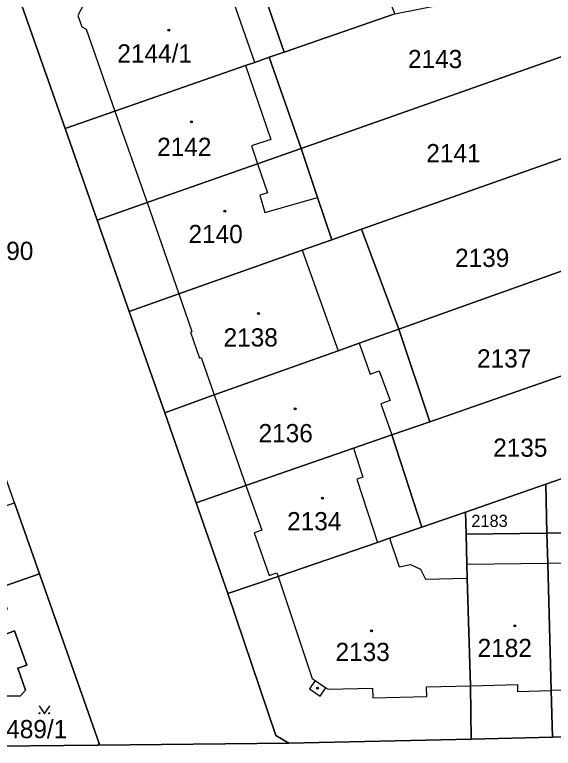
# Model space of a CAD drawing. Extents: x -596233 to -595156, y -1161235 to -1159375.
# Drawn here: x -595851.8 to -595801.6, y -1160886.7 to -1160818.3 of the extents above; entities that cross this region are included whole.
import ezdxf

# ---------------------------------------------------------------- set-up
doc = ezdxf.new("R2010")
doc.units = 0
for name, color, linetype in [('KN_CAR_KR', 7, 'Continuous'), ('KN_KULTURY', 7, 'Continuous'), ('KN_PARC_CIS_POZ', 7, 'Continuous'), ('KN_PARC_CIS_STAV', 7, 'Continuous'), ('KN_PARC_PLOCHA', 7, 'Continuous'), ('parcely_l', 7, 'Continuous')]:
    doc.layers.add(name, color=color, linetype=linetype)

msp = doc.modelspace()

# ---------------------------------------------------------------- linework, layer by layer
at = {"layer": 'KN_CAR_KR'}
for points in [[(-595829.44, -1160822.7), (-595832.08, -1160815.13)], [(-595845.38, -1160817.27), (-595845.92, -1160818.32)], [(-595845.92, -1160818.32), (-595845.55, -1160819.38)], [(-595845.55, -1160819.38), (-595845.14, -1160819.61)], [(-595845.14, -1160819.61), (-595842.47, -1160827.25)], [(-595830.29, -1160823), (-595827.95, -1160829.88)], [(-595842.47, -1160827.25), (-595839.48, -1160835.77)], [(-595827.95, -1160829.88), (-595829.75, -1160830.49)], [(-595829.75, -1160830.49), (-595829.19, -1160832.15)], [(-595829.19, -1160832.15), (-595828.24, -1160834.87)], [(-595828.24, -1160834.87), (-595828.96, -1160835.08)], [(-595828.96, -1160835.08), (-595828.49, -1160836.71)], [(-595828.49, -1160836.71), (-595823.58, -1160835.31)], [(-595839.48, -1160835.77), (-595836.53, -1160844.3)], [(-595825.01, -1160840.22), (-595821.68, -1160849.61)], [(-595836.53, -1160844.3), (-595835.3, -1160847.8)], [(-595835.3, -1160847.8), (-595835.44, -1160847.85)], [(-595835.44, -1160847.85), (-595834.58, -1160850.28)], [(-595819.7, -1160848.9), (-595818.68, -1160851.77)], [(-595834.58, -1160850.28), (-595834.44, -1160850.23)], [(-595834.44, -1160850.23), (-595833.21, -1160853.72)], [(-595818.68, -1160851.77), (-595817.84, -1160851.47)], [(-595817.84, -1160851.47), (-595816.83, -1160854.24)], [(-595833.21, -1160853.72), (-595830.27, -1160862.17)], [(-595816.83, -1160854.24), (-595817.69, -1160854.55)], [(-595817.69, -1160854.55), (-595816.66, -1160857.44)], [(-595820.25, -1160858.69), (-595819.36, -1160861.39)], [(-595819.36, -1160861.39), (-595819.94, -1160861.58)], [(-595819.94, -1160861.58), (-595818.01, -1160867.47)], [(-595830.27, -1160862.17), (-595828.79, -1160866.33)], [(-595828.79, -1160866.33), (-595829.51, -1160866.59)], [(-595829.51, -1160866.59), (-595828.1, -1160870.56)], [(-595816.88, -1160867.08), (-595815.97, -1160869.75)], [(-595815.97, -1160869.75), (-595814.93, -1160869.52)], [(-595814.93, -1160869.52), (-595814.01, -1160869.95)], [(-595809.68, -1160869.5), (-595802.13, -1160869.4)], [(-595802.13, -1160869.4), (-595794.67, -1160869.27)], [(-595828.1, -1160870.56), (-595827.39, -1160870.31)], [(-595827.39, -1160870.31), (-595827.27, -1160870.64)], [(-595814.01, -1160869.95), (-595813.52, -1160870.89)], [(-595827.27, -1160870.64), (-595824.08, -1160880.16)], [(-595813.52, -1160870.89), (-595809.65, -1160870.8)], [(-595823.82, -1160880.34), (-595824.35, -1160881.12)], [(-595824.08, -1160880.16), (-595823.82, -1160880.34)], [(-595823.82, -1160880.34), (-595822.82, -1160881.02)], [(-595809.34, -1160880.83), (-595804.96, -1160880.72)], [(-595804.96, -1160880.72), (-595804.95, -1160881.36)], [(-595824.35, -1160881.12), (-595823.36, -1160881.8)], [(-595823.36, -1160881.8), (-595822.82, -1160881.02)], [(-595822.82, -1160881.02), (-595822.61, -1160881.16)], [(-595822.61, -1160881.16), (-595818.47, -1160881.06)], [(-595818.47, -1160881.06), (-595818.45, -1160881.96)], [(-595813.43, -1160880.93), (-595809.34, -1160880.83)], [(-595813.41, -1160881.83), (-595813.43, -1160880.93)], [(-595804.95, -1160881.36), (-595801.81, -1160881.28)], [(-595798.66, -1160881.2), (-595801.81, -1160881.28)], [(-595818.45, -1160881.96), (-595813.41, -1160881.83)]]:
    msp.add_lwpolyline(points, dxfattribs=at)
at = {"layer": 'KN_KULTURY'}
msp.add_lwpolyline([(-595849.5418, -1160882.7016), (-595849.0418, -1160883.4516), (-595848.5418, -1160882.7016)], dxfattribs=at)
for centre, radius in [((-595837.45, -1160819.71), 0.09), ((-595837.45, -1160819.71), 0.0398), ((-595835.34, -1160828.24), 0.09), ((-595835.34, -1160828.24), 0.0398), ((-595832.24, -1160836.57), 0.09), ((-595832.24, -1160836.57), 0.0398), ((-595829.08, -1160846.12), 0.09), ((-595829.08, -1160846.12), 0.0398), ((-595825.67, -1160855), 0.09), ((-595825.67, -1160855), 0.0398), ((-595823.12, -1160863.34), 0.09), ((-595823.12, -1160863.34), 0.0398), ((-595805.2, -1160875.24), 0.09), ((-595805.2, -1160875.24), 0.0398), ((-595818.57, -1160875.72), 0.09), ((-595818.57, -1160875.72), 0.0398), ((-595823.59, -1160881.06), 0.09), ((-595823.59, -1160881.06), 0.0398), ((-595849.492, -1160883.4014), 0.05), ((-595848.5926, -1160883.4014), 0.05)]:
    msp.add_circle(centre, radius, dxfattribs=at)
at = {"layer": 'KN_PARC_PLOCHA'}
for points in [[(-595851.73, -1160815.7), (-595847.12, -1160828.88), (-595844.13, -1160837.41), (-595841.13, -1160845.93), (-595837.83, -1160855.37), (-595834.9, -1160863.78), (-595831.94, -1160872.24), (-595827.47, -1160885.46), (-595826.28, -1160886.2), (-595844.05, -1160886.38), (-595843.93, -1160886.23), (-595849.5, -1160870.41), (-595851.84, -1160863.77), (-595855.8, -1160852.49), (-595860.43, -1160839.35), (-595862.4, -1160833.66), (-595865.03, -1160826.08), (-595869.66, -1160812.72), (-595870.98, -1160808.89), (-595871.45, -1160807.54), (-595874.31, -1160799.57), (-595859.99, -1160792.1), (-595853.57, -1160810.43)], [(-595820.27, -1160808.95), (-595820.75, -1160809.15), (-595821.96, -1160806.33), (-595826.41, -1160808.2), (-595825.21, -1160811.03), (-595829.99, -1160812.21), (-595826.71, -1160821.75), (-595828.11, -1160822.23), (-595829.44, -1160822.7), (-595830.29, -1160823), (-595842.47, -1160827.25), (-595847.12, -1160828.88), (-595851.73, -1160815.7), (-595833.16, -1160809.18), (-595821.84, -1160805.2)], [(-595816.38, -1160818.19), (-595826.71, -1160821.75), (-595829.99, -1160812.21), (-595825.21, -1160811.03), (-595820.75, -1160809.15), (-595820.27, -1160808.95)], [(-595797.83, -1160821.11), (-595825.12, -1160830.72), (-595828.11, -1160822.23), (-595826.71, -1160821.75), (-595816.38, -1160818.19), (-595807.41, -1160816.36), (-595798.34, -1160814.51)], [(-595797.78, -1160821.87), (-595797.18, -1160829.72), (-595797.13, -1160830.35), (-595819.48, -1160838.26), (-595822.26, -1160839.24), (-595823.58, -1160835.31), (-595825.12, -1160830.72), (-595797.83, -1160821.11)], [(-595825.12, -1160830.72), (-595829.19, -1160832.15), (-595839.48, -1160835.77), (-595844.13, -1160837.41), (-595847.12, -1160828.88), (-595842.47, -1160827.25), (-595830.29, -1160823), (-595829.44, -1160822.7), (-595828.11, -1160822.23)], [(-595822.26, -1160839.24), (-595825.01, -1160840.22), (-595836.53, -1160844.3), (-595841.13, -1160845.93), (-595844.13, -1160837.41), (-595839.48, -1160835.77), (-595829.19, -1160832.15), (-595825.12, -1160830.72), (-595823.58, -1160835.31)], [(-595796.54, -1160838.04), (-595796.35, -1160840.57), (-595816.03, -1160847.59), (-595819.48, -1160838.26), (-595797.13, -1160830.35)], [(-595816.03, -1160847.59), (-595819.7, -1160848.9), (-595821.68, -1160849.61), (-595833.21, -1160853.72), (-595837.83, -1160855.37), (-595841.13, -1160845.93), (-595836.53, -1160844.3), (-595825.01, -1160840.22), (-595822.26, -1160839.24), (-595819.48, -1160838.26)], [(-595795.91, -1160846.33), (-595795.5, -1160850.08), (-595813.12, -1160856.21), (-595816.03, -1160847.59), (-595796.35, -1160840.57)], [(-595813.12, -1160856.21), (-595816.66, -1160857.44), (-595820.25, -1160858.69), (-595830.27, -1160862.17), (-595834.9, -1160863.78), (-595837.83, -1160855.37), (-595833.21, -1160853.72), (-595821.68, -1160849.61), (-595819.7, -1160848.9), (-595816.03, -1160847.59)], [(-595795.01, -1160854.52), (-595794.9, -1160859.47), (-595802.33, -1160862.05), (-595809.8, -1160864.65), (-595813.86, -1160866.04), (-595816.66, -1160857.44), (-595813.12, -1160856.21), (-595795.5, -1160850.08)], [(-595813.86, -1160866.04), (-595816.88, -1160867.08), (-595818.01, -1160867.47), (-595827.27, -1160870.64), (-595831.94, -1160872.24), (-595834.9, -1160863.78), (-595830.27, -1160862.17), (-595820.25, -1160858.69), (-595816.66, -1160857.44)], [(-595794.73, -1160866.47), (-595802.21, -1160866.6), (-595802.33, -1160862.05), (-595794.9, -1160859.47)], [(-595802.21, -1160866.6), (-595809.75, -1160866.7), (-595809.8, -1160864.65), (-595802.33, -1160862.05)], [(-595849.5, -1160870.41), (-595854.07, -1160871.98), (-595863.81, -1160875.42), (-595866.83, -1160876.49), (-595869.19, -1160869.81), (-595866.49, -1160868.86), (-595866.11, -1160868.73), (-595856.41, -1160865.34), (-595851.84, -1160863.77)], [(-595809.75, -1160866.7), (-595809.68, -1160869.5), (-595809.65, -1160870.8), (-595809.34, -1160880.83), (-595809.29, -1160885.81), (-595826.28, -1160886.2), (-595827.47, -1160885.46), (-595831.94, -1160872.24), (-595827.27, -1160870.64), (-595818.01, -1160867.47), (-595816.88, -1160867.08), (-595813.86, -1160866.04), (-595809.8, -1160864.65)], [(-595801.69, -1160885.64), (-595809.29, -1160885.81), (-595809.34, -1160880.83), (-595809.65, -1160870.8), (-595809.68, -1160869.5), (-595809.75, -1160866.7), (-595802.21, -1160866.6), (-595802.13, -1160869.4), (-595801.81, -1160881.28)], [(-595794.3, -1160885.47), (-595801.69, -1160885.64), (-595801.81, -1160881.28), (-595802.13, -1160869.4), (-595802.21, -1160866.6), (-595794.73, -1160866.47), (-595794.67, -1160869.27), (-595794.35, -1160880.45)], [(-595844.05, -1160886.38), (-595872.49, -1160886.67), (-595872.74, -1160881.73), (-595863.36, -1160881.65), (-595863.36, -1160881.85), (-595851.28, -1160881.78), (-595850.8, -1160881.24), (-595851.52, -1160879.2), (-595850.69, -1160878.91), (-595851.82, -1160875.71), (-595852.65, -1160876.01), (-595853.36, -1160873.99), (-595852.51, -1160873.69), (-595852.98, -1160872.36), (-595853.83, -1160872.66), (-595854.07, -1160871.98), (-595849.5, -1160870.41), (-595843.93, -1160886.23)], [(-595872.74, -1160881.73), (-595872.89, -1160878.63), (-595866.83, -1160876.49), (-595863.81, -1160875.42), (-595862.24, -1160879.97), (-595852.66, -1160876.68), (-595854.07, -1160871.98), (-595853.83, -1160872.66), (-595852.98, -1160872.36), (-595852.51, -1160873.69), (-595853.36, -1160873.99), (-595852.65, -1160876.01), (-595851.82, -1160875.71), (-595850.69, -1160878.91), (-595851.52, -1160879.2), (-595850.8, -1160881.24), (-595851.28, -1160881.78), (-595863.36, -1160881.85), (-595863.36, -1160881.65)]]:
    msp.add_lwpolyline(points, close=True, dxfattribs=at)
msp.add_lwpolyline([(-595872.49, -1160886.67), (-595844.05, -1160886.38), (-595826.28, -1160886.2), (-595809.29, -1160885.81), (-595801.69, -1160885.64), (-595794.3, -1160885.47), (-595786.8, -1160885.3), (-595771.81, -1160884.95), (-595751.54, -1160884.49), (-595738.34, -1160884.22)], dxfattribs=at)
at = {"layer": 'parcely_l'}
for points in [[(-595826.71, -1160821.75), (-595829.99, -1160812.21), (-595825.21, -1160811.03)], [(-595851.73, -1160815.7), (-595847.12, -1160828.88)], [(-595826.71, -1160821.75), (-595816.38, -1160818.19)], [(-595797.83, -1160821.11), (-595825.12, -1160830.72)], [(-595828.11, -1160822.23), (-595826.71, -1160821.75)], [(-595847.12, -1160828.88), (-595842.47, -1160827.25), (-595830.29, -1160823), (-595829.44, -1160822.7), (-595828.11, -1160822.23)], [(-595825.12, -1160830.72), (-595828.11, -1160822.23)], [(-595844.13, -1160837.41), (-595847.12, -1160828.88)], [(-595844.13, -1160837.41), (-595839.48, -1160835.77), (-595829.19, -1160832.15), (-595825.12, -1160830.72)], [(-595825.12, -1160830.72), (-595823.58, -1160835.31), (-595822.26, -1160839.24)], [(-595819.48, -1160838.26), (-595797.13, -1160830.35)], [(-595841.13, -1160845.93), (-595844.13, -1160837.41)], [(-595819.48, -1160838.26), (-595822.26, -1160839.24)], [(-595816.03, -1160847.59), (-595819.48, -1160838.26)], [(-595822.26, -1160839.24), (-595825.01, -1160840.22), (-595836.53, -1160844.3), (-595841.13, -1160845.93)], [(-595816.03, -1160847.59), (-595796.35, -1160840.57)], [(-595841.13, -1160845.93), (-595837.83, -1160855.37)], [(-595837.83, -1160855.37), (-595833.21, -1160853.72), (-595821.68, -1160849.61), (-595819.7, -1160848.9), (-595816.03, -1160847.59)], [(-595813.12, -1160856.21), (-595816.03, -1160847.59)], [(-595795.5, -1160850.08), (-595813.12, -1160856.21)], [(-595837.83, -1160855.37), (-595834.9, -1160863.78)], [(-595816.66, -1160857.44), (-595813.12, -1160856.21)], [(-595834.9, -1160863.78), (-595830.27, -1160862.17), (-595820.25, -1160858.69), (-595816.66, -1160857.44)], [(-595813.86, -1160866.04), (-595816.66, -1160857.44)], [(-595802.33, -1160862.05), (-595794.9, -1160859.47)], [(-595802.33, -1160862.05), (-595809.8, -1160864.65)], [(-595802.21, -1160866.6), (-595802.33, -1160862.05)], [(-595849.5, -1160870.41), (-595851.84, -1160863.77)], [(-595831.94, -1160872.24), (-595834.9, -1160863.78)], [(-595809.8, -1160864.65), (-595813.86, -1160866.04)], [(-595809.8, -1160864.65), (-595809.75, -1160866.7)], [(-595813.86, -1160866.04), (-595816.88, -1160867.08), (-595818.01, -1160867.47), (-595827.27, -1160870.64), (-595831.94, -1160872.24)], [(-595802.21, -1160866.6), (-595809.75, -1160866.7)], [(-595809.75, -1160866.7), (-595809.68, -1160869.5), (-595809.65, -1160870.8), (-595809.34, -1160880.83), (-595809.29, -1160885.81)], [(-595794.73, -1160866.47), (-595802.21, -1160866.6)], [(-595801.69, -1160885.64), (-595801.81, -1160881.28), (-595802.13, -1160869.4), (-595802.21, -1160866.6)], [(-595849.5, -1160870.41), (-595854.07, -1160871.98)], [(-595844.05, -1160886.38), (-595843.93, -1160886.23), (-595849.5, -1160870.41)], [(-595854.07, -1160871.98), (-595853.83, -1160872.66), (-595852.98, -1160872.36), (-595852.51, -1160873.69), (-595853.36, -1160873.99), (-595852.65, -1160876.01), (-595851.82, -1160875.71), (-595850.69, -1160878.91), (-595851.52, -1160879.2), (-595850.8, -1160881.24), (-595851.28, -1160881.78), (-595863.36, -1160881.85), (-595863.36, -1160881.65), (-595872.74, -1160881.73)], [(-595826.28, -1160886.2), (-595827.47, -1160885.46), (-595831.94, -1160872.24)], [(-595801.69, -1160885.64), (-595794.3, -1160885.47)], [(-595844.05, -1160886.38), (-595826.28, -1160886.2)], [(-595826.28, -1160886.2), (-595809.29, -1160885.81)], [(-595809.29, -1160885.81), (-595801.69, -1160885.64)], [(-595872.49, -1160886.67), (-595844.05, -1160886.38)]]:
    msp.add_lwpolyline(points, dxfattribs=at)

# ---------------------------------------------------------------- texts
at = {"layer": 'KN_PARC_CIS_POZ'}
for s, height, p in [('2143', 1.7, (-595815.1666, -1160823.24)), ('2141', 1.7, (-595813.4566, -1160832.02)), ('1490', 1.7, (-595855.1266, -1160841.13)), ('2139', 1.7, (-595810.7766, -1160841.78)), ('2137', 1.7, (-595808.7266, -1160851.16)), ('2135', 1.7, (-595807.2266, -1160859.48)), ('2183', 1.14, (-595809.26, -1160866.03)), ('1489/1', 1.7, (-595853.8666, -1160885.73))]:
    msp.add_text(s, height=height, dxfattribs=at).set_placement(p)
at = {"layer": 'KN_PARC_CIS_STAV'}
for s, p in [('2144/1', (-595842.2466, -1160822.72)), ('2142', (-595838.5366, -1160831.43)), ('2140', (-595835.6166, -1160839.56)), ('2138', (-595832.3466, -1160849.2)), ('2136', (-595829.0866, -1160858.13)), ('2134', (-595826.4266, -1160866.34)), ('2182', (-595808.6766, -1160878.16)), ('2133', (-595821.9166, -1160878.53))]:
    msp.add_text(s, height=1.7, dxfattribs=at).set_placement(p)

doc.saveas('drawing.dxf')
